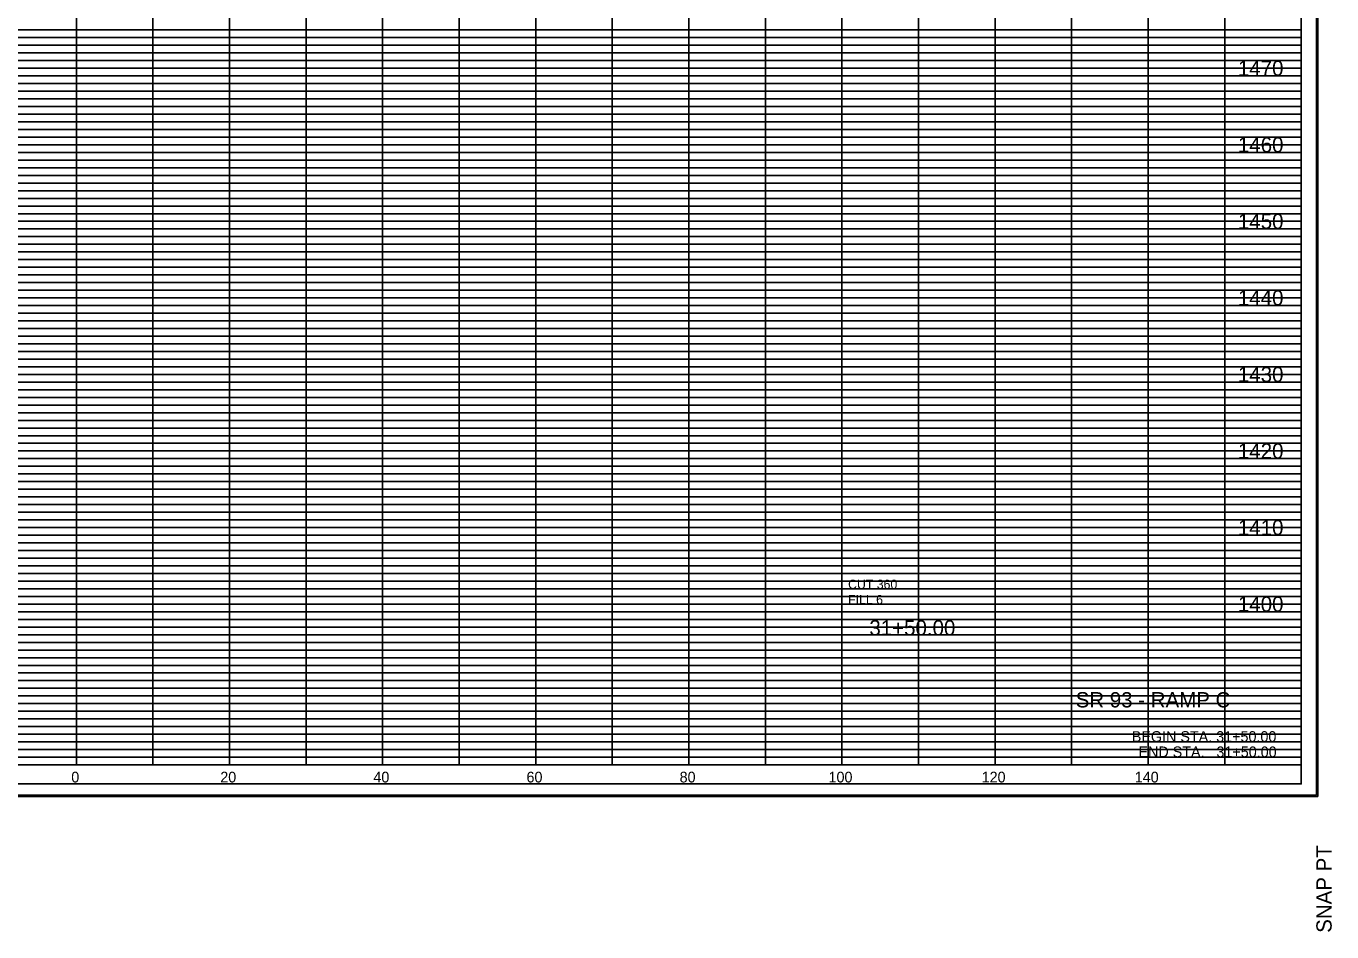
# Model space of a CAD drawing. Extents: x 980 to 2064, y 978 to 2267.
# Drawn here: x 1153.4 to 1324, y 1758.2 to 1876.5 of the extents above; entities that cross this region are included whole.
import ezdxf

# ---------------------------------------------------------------- set-up
doc = ezdxf.new("R2010")
doc.units = 0
for name, color, linetype in [('Default', 7, 'Continuous'), ('DESIGN - SHEET - Corner Text', 7, 'Continuous'), ('DESIGN - SHEET - Light Grid', 7, 'Continuous'), ('DESIGN - SHEET - Linework', 7, 'Continuous'), ('DESIGN - SHEET - Plot Shape', 7, 'Continuous'), ('DESIGN - TYPICAL - Text', 7, 'Continuous')]:
    doc.layers.add(name, color=color, linetype=linetype)

# ---------------------------------------------------------------- blocks, each defined once
blk = doc.blocks.new('XSTSHT')
at = {"layer": 'DESIGN - SHEET - Light Grid'}
for p, q in [((8, 9.6), (16, 9.6)), ((16, 9.6), (24, 9.6)), ((24, 9.6), (32, 9.6)), ((8, 9.5), (16, 9.5)), ((8, 9.4), (16, 9.4)), ((16, 9.5), (24, 9.5)), ((16, 9.4), (24, 9.4)), ((24, 9.5), (32, 9.5)), ((24, 9.4), (32, 9.4)), ((8, 9.3), (16, 9.3)), ((16, 9.3), (24, 9.3)), ((24, 9.3), (32, 9.3)), ((8, 9.2), (16, 9.2)), ((8, 9.1), (16, 9.1)), ((16, 9.2), (24, 9.2)), ((16, 9.1), (24, 9.1)), ((24, 9.2), (32, 9.2)), ((24, 9.1), (32, 9.1)), ((8, 8.9), (16, 8.9)), ((16, 8.9), (24, 8.9)), ((24, 8.9), (32, 8.9)), ((8, 8.8), (16, 8.8)), ((8, 8.7), (16, 8.7)), ((16, 8.8), (24, 8.8)), ((16, 8.7), (24, 8.7)), ((24, 8.8), (32, 8.8)), ((24, 8.7), (32, 8.7)), ((8, 8.6), (16, 8.6)), ((16, 8.6), (24, 8.6)), ((24, 8.6), (32, 8.6)), ((8, 8.5), (16, 8.5)), ((8, 8.4), (16, 8.4)), ((16, 8.5), (24, 8.5)), ((16, 8.4), (24, 8.4)), ((24, 8.5), (32, 8.5)), ((24, 8.4), (32, 8.4)), ((8, 8.3), (16, 8.3)), ((8, 8.2), (16, 8.2)), ((16, 8.3), (24, 8.3)), ((16, 8.2), (24, 8.2)), ((24, 8.3), (32, 8.3)), ((24, 8.2), (32, 8.2)), ((8, 8.1), (16, 8.1)), ((16, 8.1), (24, 8.1)), ((24, 8.1), (32, 8.1)), ((8, 7.9), (16, 7.9)), ((16, 7.9), (24, 7.9)), ((24, 7.9), (32, 7.9)), ((8, 7.8), (16, 7.8)), ((8, 7.7), (16, 7.7)), ((16, 7.8), (24, 7.8)), ((16, 7.7), (24, 7.7)), ((24, 7.8), (32, 7.8)), ((24, 7.7), (32, 7.7)), ((8, 7.6), (16, 7.6)), ((16, 7.6), (24, 7.6)), ((24, 7.6), (32, 7.6)), ((8, 7.5), (16, 7.5)), ((8, 7.4), (16, 7.4)), ((16, 7.5), (24, 7.5)), ((16, 7.4), (24, 7.4)), ((24, 7.5), (32, 7.5)), ((24, 7.4), (32, 7.4)), ((8, 7.3), (16, 7.3)), ((8, 7.2), (16, 7.2)), ((16, 7.3), (24, 7.3)), ((16, 7.2), (24, 7.2)), ((24, 7.3), (32, 7.3)), ((24, 7.2), (32, 7.2)), ((8, 7.1), (16, 7.1)), ((16, 7.1), (24, 7.1)), ((24, 7.1), (32, 7.1)), ((8, 6.9), (16, 6.9)), ((16, 6.9), (24, 6.9)), ((24, 6.9), (32, 6.9)), ((8, 6.8), (16, 6.8)), ((8, 6.7), (16, 6.7)), ((16, 6.8), (24, 6.8)), ((16, 6.7), (24, 6.7)), ((24, 6.8), (32, 6.8)), ((24, 6.7), (32, 6.7)), ((8, 6.6), (16, 6.6)), ((8, 6.5), (16, 6.5)), ((16, 6.6), (24, 6.6)), ((16, 6.5), (24, 6.5)), ((24, 6.6), (32, 6.6)), ((24, 6.5), (32, 6.5)), ((8, 6.4), (16, 6.4)), ((16, 6.4), (24, 6.4)), ((24, 6.4), (32, 6.4)), ((8, 6.3), (16, 6.3)), ((8, 6.2), (16, 6.2)), ((16, 6.3), (24, 6.3)), ((16, 6.2), (24, 6.2)), ((24, 6.3), (32, 6.3)), ((24, 6.2), (32, 6.2)), ((8, 6.1), (16, 6.1)), ((16, 6.1), (24, 6.1)), ((24, 6.1), (32, 6.1)), ((8, 5.9), (16, 5.9)), ((8, 5.8), (16, 5.8)), ((16, 5.9), (24, 5.9)), ((16, 5.8), (24, 5.8)), ((24, 5.9), (32, 5.9)), ((24, 5.8), (32, 5.8)), ((8, 5.7), (16, 5.7)), ((16, 5.7), (24, 5.7)), ((24, 5.7), (32, 5.7)), ((8, 5.6), (16, 5.6)), ((8, 5.5), (16, 5.5)), ((16, 5.6), (24, 5.6)), ((16, 5.5), (24, 5.5)), ((24, 5.6), (32, 5.6)), ((24, 5.5), (32, 5.5)), ((8, 5.4), (16, 5.4)), ((8, 5.3), (16, 5.3)), ((16, 5.4), (24, 5.4)), ((16, 5.3), (24, 5.3)), ((24, 5.4), (32, 5.4)), ((24, 5.3), (32, 5.3)), ((8, 5.2), (16, 5.2)), ((16, 5.2), (24, 5.2)), ((24, 5.2), (32, 5.2)), ((8, 5.1), (16, 5.1)), ((16, 5.1), (24, 5.1)), ((24, 5.1), (32, 5.1)), ((8, 4.9), (16, 4.9)), ((8, 4.8), (16, 4.8)), ((16, 4.9), (24, 4.9)), ((16, 4.8), (24, 4.8)), ((24, 4.9), (32, 4.9)), ((24, 4.8), (32, 4.8)), ((8, 4.7), (16, 4.7)), ((16, 4.7), (24, 4.7)), ((24, 4.7), (32, 4.7)), ((8, 4.6), (16, 4.6)), ((8, 4.5), (16, 4.5)), ((16, 4.6), (24, 4.6)), ((16, 4.5), (24, 4.5)), ((24, 4.6), (32, 4.6)), ((24, 4.5), (32, 4.5)), ((8, 4.4), (16, 4.4)), ((8, 4.3), (16, 4.3)), ((16, 4.4), (24, 4.4)), ((16, 4.3), (24, 4.3)), ((24, 4.4), (32, 4.4)), ((24, 4.3), (32, 4.3)), ((8, 4.2), (16, 4.2)), ((8, 4.1), (16, 4.1)), ((16, 4.2), (24, 4.2)), ((16, 4.1), (24, 4.1)), ((24, 4.2), (32, 4.2)), ((24, 4.1), (32, 4.1)), ((8, 3.9), (16, 3.9)), ((8, 3.8), (16, 3.8)), ((16, 3.9), (24, 3.9)), ((16, 3.8), (24, 3.8)), ((24, 3.9), (32, 3.9)), ((24, 3.8), (32, 3.8)), ((8, 3.7), (16, 3.7)), ((8, 3.6), (16, 3.6)), ((16, 3.7), (24, 3.7)), ((16, 3.6), (24, 3.6)), ((24, 3.7), (32, 3.7)), ((24, 3.6), (32, 3.6)), ((8, 3.5), (16, 3.5)), ((16, 3.5), (24, 3.5)), ((24, 3.5), (32, 3.5)), ((8, 3.4), (16, 3.4)), ((8, 3.3), (16, 3.3)), ((16, 3.4), (24, 3.4)), ((16, 3.3), (24, 3.3)), ((24, 3.4), (32, 3.4)), ((24, 3.3), (32, 3.3)), ((8, 3.2), (16, 3.2)), ((8, 3.1), (16, 3.1)), ((16, 3.2), (24, 3.2)), ((16, 3.1), (24, 3.1)), ((24, 3.2), (32, 3.2)), ((24, 3.1), (32, 3.1)), ((8, 2.9), (16, 2.9)), ((16, 2.9), (24, 2.9)), ((24, 2.9), (32, 2.9)), ((8, 2.8), (16, 2.8)), ((16, 2.8), (24, 2.8)), ((24, 2.8), (32, 2.8)), ((8, 2.7), (16, 2.7)), ((8, 2.6), (16, 2.6)), ((16, 2.7), (24, 2.7)), ((16, 2.6), (24, 2.6)), ((24, 2.7), (32, 2.7)), ((24, 2.6), (32, 2.6)), ((8, 2.5), (16, 2.5)), ((8, 2.4), (16, 2.4)), ((16, 2.5), (24, 2.5)), ((16, 2.4), (24, 2.4)), ((24, 2.5), (32, 2.5)), ((24, 2.4), (32, 2.4)), ((8, 2.3), (16, 2.3)), ((16, 2.3), (24, 2.3)), ((24, 2.3), (32, 2.3)), ((8, 2.2), (16, 2.2)), ((8, 2.1), (16, 2.1)), ((16, 2.2), (24, 2.2)), ((16, 2.1), (24, 2.1)), ((24, 2.2), (32, 2.2)), ((24, 2.1), (32, 2.1)), ((8, 1.9), (16, 1.9)), ((16, 1.9), (24, 1.9)), ((24, 1.9), (32, 1.9)), ((8, 1.8), (16, 1.8)), ((16, 1.8), (24, 1.8)), ((24, 1.8), (32, 1.8)), ((8, 1.7), (16, 1.7)), ((8, 1.6), (16, 1.6)), ((16, 1.7), (24, 1.7)), ((16, 1.6), (24, 1.6)), ((24, 1.7), (32, 1.7)), ((24, 1.6), (32, 1.6)), ((8, 1.5), (16, 1.5)), ((8, 1.4), (16, 1.4)), ((16, 1.5), (24, 1.5)), ((16, 1.4), (24, 1.4)), ((24, 1.5), (32, 1.5)), ((24, 1.4), (32, 1.4)), ((8, 1.3), (16, 1.3)), ((8, 1.2), (16, 1.2)), ((16, 1.3), (24, 1.3)), ((16, 1.2), (24, 1.2)), ((24, 1.3), (32, 1.3)), ((24, 1.2), (32, 1.2)), ((8, 1.1), (16, 1.1)), ((16, 1.1), (24, 1.1)), ((24, 1.1), (32, 1.1)), ((8, 0.9), (16, 0.9)), ((16, 0.9), (24, 0.9)), ((24, 0.9), (32, 0.9)), ((8, 0.8), (16, 0.8)), ((8, 0.7), (16, 0.7)), ((16, 0.8), (24, 0.8)), ((16, 0.7), (24, 0.7)), ((24, 0.8), (32, 0.8)), ((24, 0.7), (32, 0.7)), ((8, 0.6), (16, 0.6)), ((16, 0.6), (24, 0.6)), ((24, 0.6), (32, 0.6)), ((8, 0.5), (16, 0.5)), ((8, 0.4), (16, 0.4)), ((16, 0.5), (24, 0.5)), ((16, 0.4), (24, 0.4)), ((24, 0.5), (32, 0.5)), ((24, 0.4), (32, 0.4)), ((8, 0.3), (16, 0.3)), ((8, 0.2), (16, 0.2)), ((16, 0.3), (24, 0.3)), ((16, 0.2), (24, 0.2)), ((24, 0.3), (32, 0.3)), ((24, 0.2), (32, 0.2)), ((8, 0.1), (16, 0.1)), ((16, 0.1), (24, 0.1)), ((24, 0.1), (32, 0.1))]:
    blk.add_line(p, q, dxfattribs=at)
at = {"layer": 'DESIGN - SHEET - Linework'}
for p, q in [((32.217, 21.414), (32.217, -0.414)), ((16, 0), (16, 21)), ((17, 0), (17, 21)), ((18, 0), (18, 21)), ((19, 0), (19, 21)), ((20, 0), (20, 21)), ((21, 0), (21, 21)), ((22, 0), (22, 21)), ((23, 0), (23, 21)), ((24, 0), (24, 21)), ((25, 0), (25, 21)), ((26, 0), (26, 21)), ((27, 0), (27, 21)), ((28, 0), (28, 20)), ((29, 0), (29, 20)), ((30, 0), (30, 20)), ((31, 0), (31, 20)), ((0, 9), (32, 9)), ((0, 8), (32, 8)), ((0, 7), (32, 7)), ((0, 6), (32, 6)), ((0, 5), (32, 5)), ((0, 4), (32, 4)), ((0, 3), (32, 3)), ((0, 2), (32, 2)), ((0, 1), (32, 1)), ((-1.823, -0.414), (32.217, -0.414))]:
    blk.add_line(p, q, dxfattribs=at)
blk.add_lwpolyline([(0, 21), (0, 0), (32, 0), (32, 21), (0, 21)], dxfattribs=at)
at = {"layer": 'DESIGN - SHEET - Plot Shape'}
for points in [[(-1.803, 21.394), (32.197, 21.394), (32.197, -0.394), (-1.803, -0.394)], [(-0.85, 21), (32, 21), (32, -0.25), (-0.85, -0.25)]]:
    blk.add_lwpolyline(points, close=True, dxfattribs=at)
at = {"layer": 'DESIGN - SHEET - Corner Text'}
blk.add_text('SNAP PT  ', height=0.2, rotation=90, dxfattribs=at).set_placement((32.397, -2.194))

msp = doc.modelspace()

# ---------------------------------------------------------------- block references
at = {"layer": 'Default', "xscale": 10, "yscale": 10}
msp.add_blockref('XSTSHT', (1000, 1780), dxfattribs=at)

# ---------------------------------------------------------------- texts
at = {"layer": 'Default'}
for s, height, p in [('     1470     ', 2, (1308.01, 1870)), ('     1460     ', 2, (1308.01, 1860)), ('     1450     ', 2, (1308.01, 1850)), ('     1440     ', 2, (1308.01, 1840)), ('     1430     ', 2, (1308.01, 1830)), ('     1420     ', 2, (1308.01, 1820)), ('     1410     ', 2, (1308.01, 1810)), ('     1400     ', 2, (1308.01, 1800)), ('     31+50.00     ', 2, (1259.87, 1796.9)), ('     0     ', 1.4, (1156.74, 1777.7)), ('     0     ', 1.4, (1156.74, 1777.7)), ('     20     ', 1.4, (1176.2, 1777.7)), ('     40     ', 1.4, (1196.2, 1777.7)), ('     60     ', 1.4, (1216.2, 1777.7)), ('     80     ', 1.4, (1236.2, 1777.7)), ('     100     ', 1.4, (1255.65, 1777.7)), ('     120     ', 1.4, (1275.65, 1777.7)), ('     140     ', 1.4, (1295.65, 1777.7))]:
    msp.add_text(s, height=height, dxfattribs=at).set_placement(p)
at = {"layer": 'DESIGN - SHEET - Corner Text'}
for s, height, p in [('SR 93 - RAMP C', 2, (1290.53, 1787.5)), ('BEGIN STA. 31+50.00', 1.4, (1297.86, 1783)), ('END STA.   31+50.00', 1.4, (1298.73, 1781))]:
    msp.add_text(s, height=height, dxfattribs=at).set_placement(p)
at = {"layer": 'DESIGN - TYPICAL - Text'}
for s, p in [('CUT 360', (1260.81, 1802.99)), ('FILL 6', (1260.81, 1800.99))]:
    msp.add_text(s, height=1.2, dxfattribs=at).set_placement(p)

doc.saveas('drawing.dxf')
